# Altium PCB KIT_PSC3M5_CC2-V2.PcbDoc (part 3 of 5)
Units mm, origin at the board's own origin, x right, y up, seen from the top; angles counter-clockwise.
Board outline 131.5 x 87 mm, 6 copper layers (Top Layer, Int1 (GND), Int2 (Sign), Int3 (Sign), Int4 (PWR), Bottom Layer), stack 1.551 mm thick; 371 components, 253 nets, 1359 pads, 837 vias.
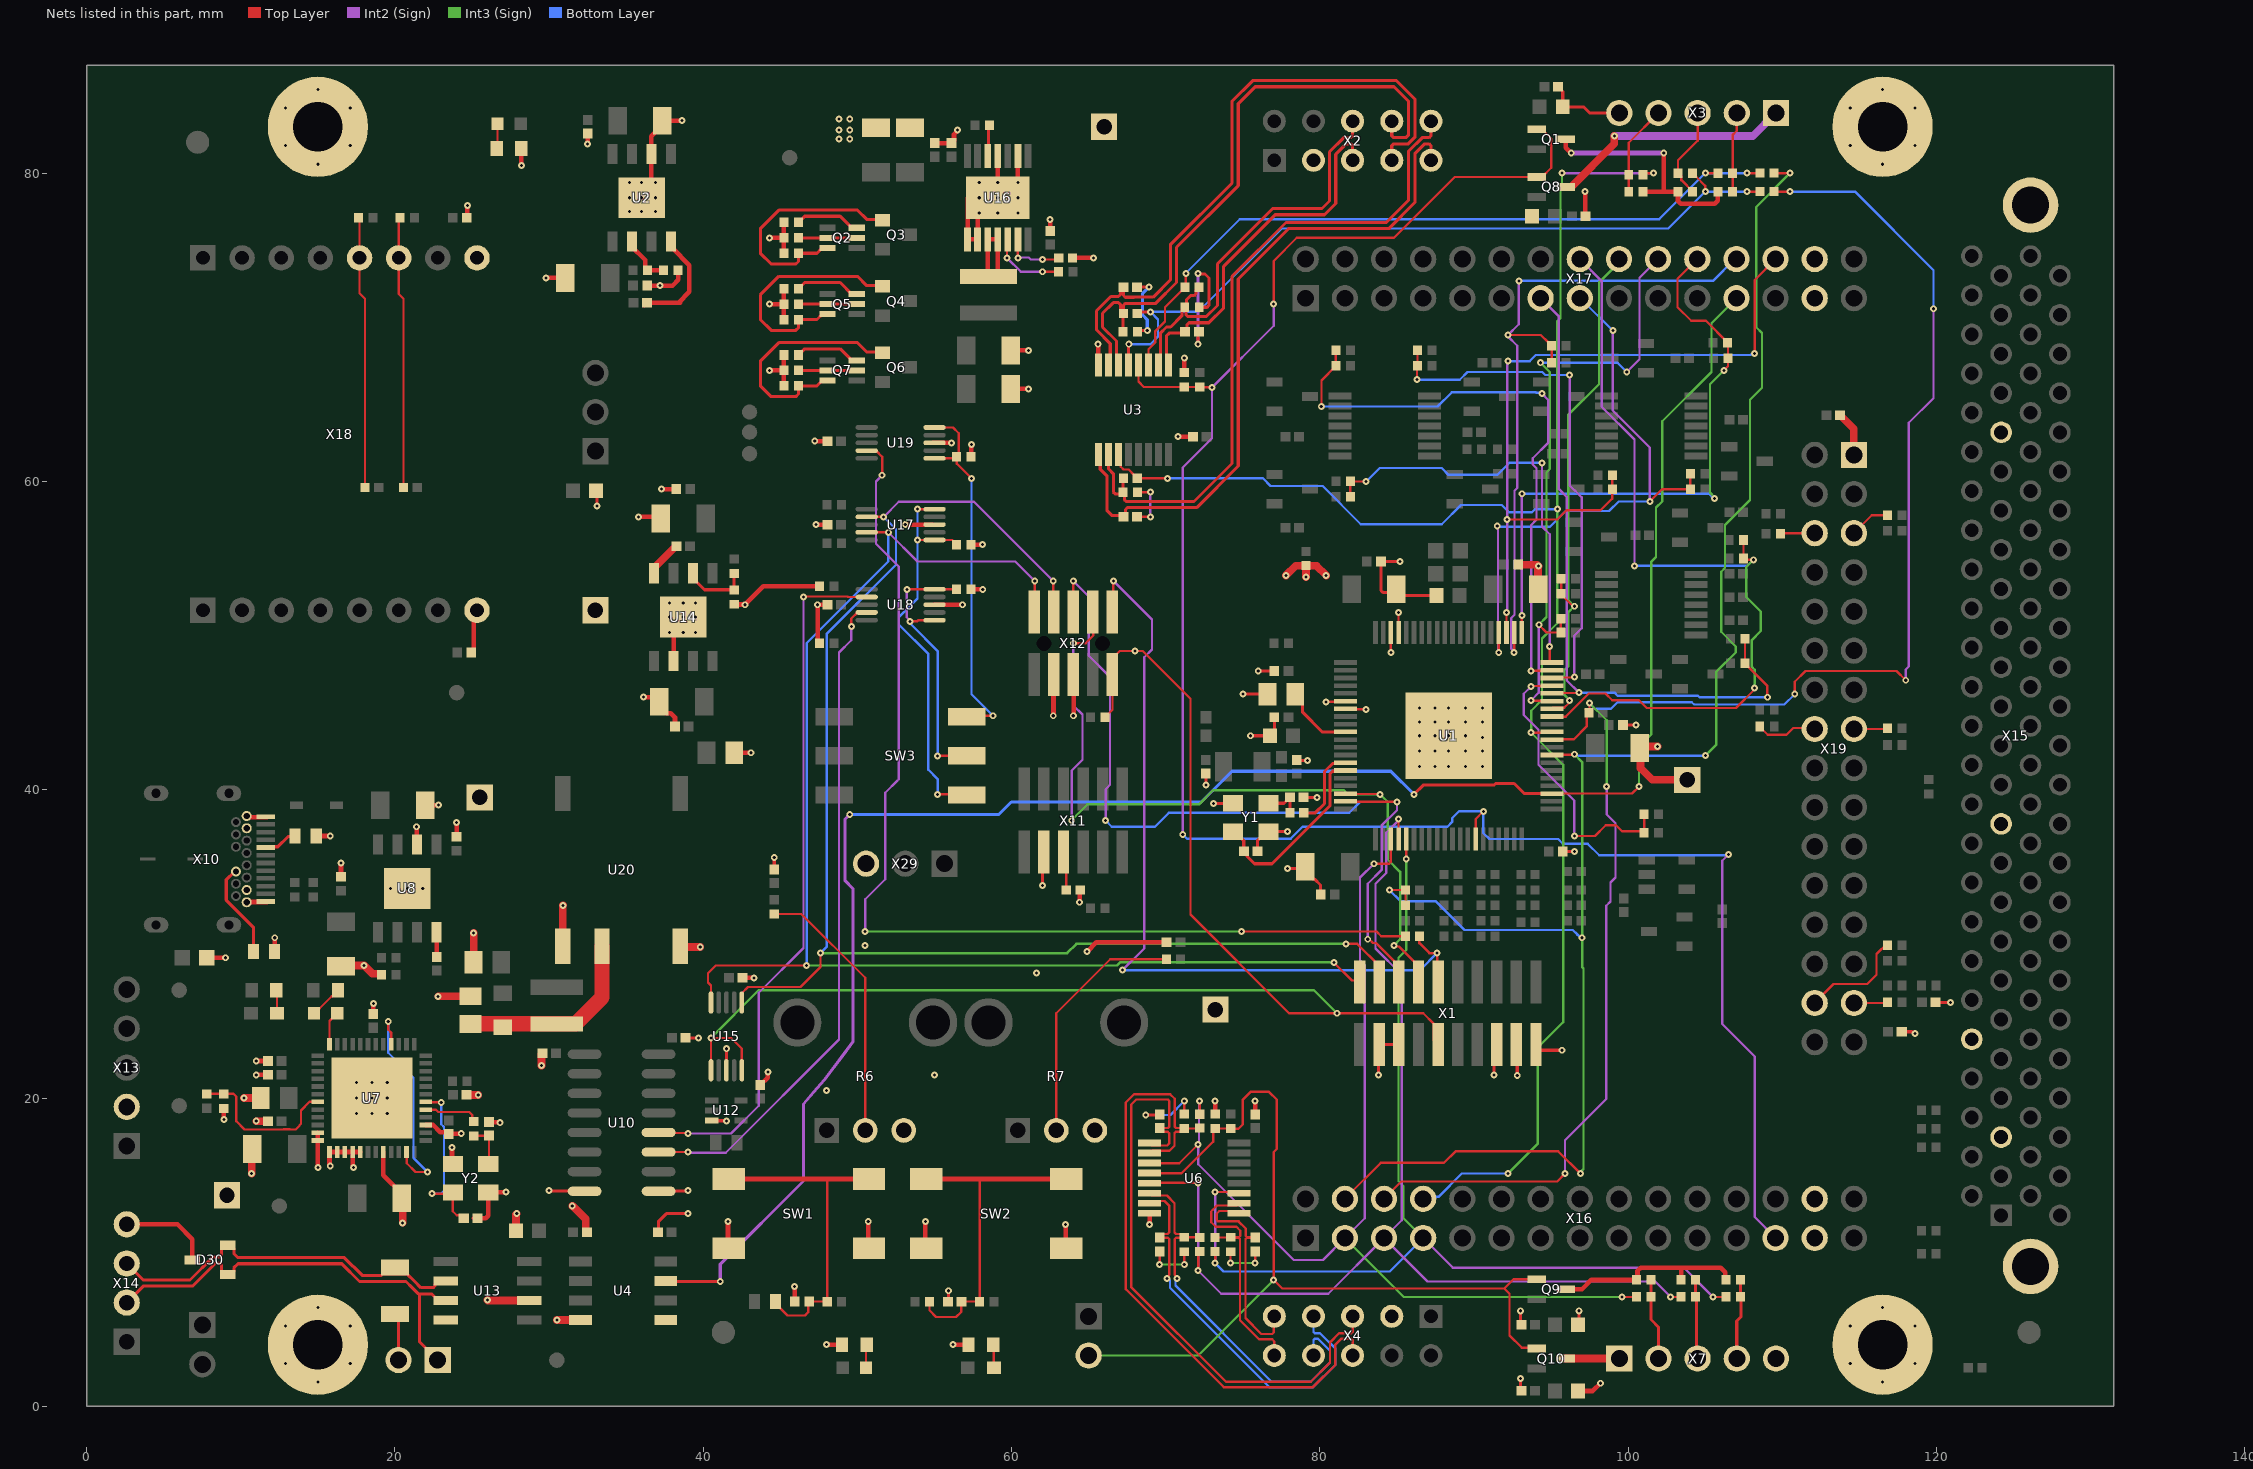
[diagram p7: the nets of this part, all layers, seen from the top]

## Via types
v1: diameter 0.45, hole 0.2, Top Layer to Bottom Layer, tented both sides, 833 vias
v2: diameter 0.55, hole 0.2, Top Layer to Bottom Layer, tented both sides, 4 vias

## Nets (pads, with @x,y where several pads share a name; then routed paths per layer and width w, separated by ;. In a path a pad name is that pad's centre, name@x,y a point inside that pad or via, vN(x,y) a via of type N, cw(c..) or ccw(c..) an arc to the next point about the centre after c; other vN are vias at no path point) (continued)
CAN1_TX: U1.43 U4.7 X17.23 | length 125.6
  Top Layer w0.15: U1.43@95.05,39.75 100.25,39.75 v1(100.7,40.2)
  Top Layer w0.2: U4.7@37.57,8.135 37.605,8.1 v1(41.1,8.1) ; v1(86.1,39.7) 86.7,40.3 91.293,40.3 91.393,40.4 92.6,40.4 93.25,39.75 U1.43@95.05,39.75
  Int2 (Sign) w0.2: v1@41.145,8.145 v1(41.1,8.1) 41.1,9.223 46.5,14.623 46.5,19.606 ccw(c11.001,50.974) 49.7,23.651 49.7,33.589 49.2,34.089 49.2,38.1 v1(49.5,38.4)
  Int3 (Sign) w0.15: v1(100.7,40.2) 100.7,42.8 101.5,43.6 101.5,54.8 101.8,55.1 101.8,58.3 102.2,58.7 102.2,63.9 105.4,67.1 105.4,70.266 X17.23@107.016,71.882
  Bottom Layer w0.2: v1(49.5,38.4) 59.186,38.4 59.986,39.2 72.3,39.2 74.3,41.2 84.6,41.2 v1(86.1,39.7)
CAN_N: D30.2 R73.2 U13.6 X14.3 | length 24.6
  Top Layer w0.2: X14.3@2.6,9.27 3.67,8.2 6.704,8.2 8.204,9.7 8.633,9.7 8.75,9.817 8.75,10.25 8.95,10.45 D30.2@9.15,10.45 9.35,10.45 9.55,10.25 9.55,9.916 9.816,9.65 16.716,9.65 17.866,8.5 19.125,8.5 19.2,8.575 R73.2@20.8,8.575 ; R73.2@20.375,9 R73.2@20.8,8.575 ; U13.6@23.3,8.135 22.8,8.135 22.6,7.935 22.6,7.817 22.483,7.7 21.783,7.7 21.679,7.7 21.279,8.1 21.275,8.1 R73.2@20.8,8.575
CAN_P: D30.1 U13.7 X14.2 X28.1 | length 28.5
  Top Layer w0.2: X14.2@2.6,6.73 3.67,7.8 6.869,7.8 8.369,9.3 8.633,9.3 8.75,9.183 8.75,8.75 8.95,8.55 D30.1@9.15,8.55 9.35,8.55 9.55,8.75 9.55,8.984 9.816,9.25 16.55,9.25 17.7,8.1 20.709,8.1 21.109,7.7 21.114,7.7 21.514,7.3 22.365,7.3 22.8,6.865 U13.7@23.3,6.865 ; 21.6,7.3 21.6,4.17 X28.1@22.77,3
CON_RESET#: R11.1 U19.9 | length 69.8
  Top Layer w0.15: U19.9@50.705,62 51.205,62 51.6,61.605 v1(51.6,60.4) ; v1(74.9,30.8) 83.672,30.8 83.972,30.5 R11.1@85.55,30.5
  Int2 (Sign) w0.15: v1(50.5,30.8) 50.5,32.9 51.8,34.2 51.8,39.8 ; v1(51.6,60.4) 51.2,60 51.2,55.96 52.675,54.485 52.675,40.675 51.8,39.8 ; 52.6,40.6 51.8,39.8
  Int3 (Sign) w0.15: v1(50.5,30.8) v1(74.9,30.8)
CON_SWDCLK: U15.6 U17.7 X1.4 X12.4 | length 92.8
  Top Layer w0.15: U15.6@42.5,26.2 42.5,26.8 42.9,27.2 46.3,27.2 47.6,28.5 v1(47.6,29.4) ; U17.7@50.705,57.7 v1(51.7,57.7) ; X12.4@62.7,51.4 v1(62.7,53.54) ; v1(81.7,30) 82.415,30 83.855,28.56 X1.4@83.855,27.535
  Int2 (Sign) w0.15: v1(51.7,57.7) 52.675,58.675 57.565,58.675 v1(62.7,53.54)
  Int3 (Sign) w0.15: v1(47.6,29.4) 63.6,29.4 64.2,30 v1(81.7,30)
  Bottom Layer w0.15: v1(47.6,29.4) 48,29.8 48,50.1 52.5,54.6 52.5,56.9 v1(51.7,57.7)
CON_SWDIO: U15.10 U17.9 X1.2 X12.2 | length 89.8
  Top Layer w0.15: U15.10@40.5,26.2 40.5,27.3 40.3,27.5 40.3,28.1 40.8,28.6 v1(46.7,28.6) ; U17.9@50.6,56.7 v1(52,56.7) ; X12.2@61.5,51.4 v1(61.5,53.54) ; v1(80.9,28.8) 82.078,27.622 82.498,27.622 X1.2@82.585,27.535
  Int2 (Sign) w0.15: v1(52,56.7) 53.895,54.805 60.235,54.805 v1(61.5,53.54)
  Int3 (Sign) w0.15: v1(46.7,28.6) 66.828,28.6 67.028,28.8 v1(80.9,28.8)
  Bottom Layer w0.15: v1(46.7,28.6) 46.7,49.5 52,54.8 v1(52,56.7) ; v1(61.5,53.54) v1@61.5,53.612
CS: U7.23 U7.40 | length 14.7
  Top Layer w0.15: v1(19.564,24.964) 19.564,24.436 19.75,24.25 U7.40@19.75,23.5 ; U7.23@20.75,16.5 20.765,16.485 20.765,15.765 21.328,15.202 v1(22.1,15.202)
  Bottom Layer w0.15: v1(19.564,24.964) 19.564,22.936 21.2,21.3 21.2,16.102 v1(22.1,15.202)
DEBUG_LED#: D5.1 U7.48 | length 2.2
  Top Layer w0.15: U7.48@15.75,23.5 15.75,25 D5.1@16.25,25.5
ECO_IN: R8.1 U1.14 | length 5.3
  Top Layer w0.2: R8.1@78.95,38.5 79.7,38.5 80.3,39.1 80.3,41.178 80.822,41.7 81.6,41.7 U1.14@81.65,41.75
ECO_OUT: C86.2 U1.15 Y1.3 | length 12.4
  Top Layer w0.2: Y1.3@74.35,37.275 74.475,37.275 75.06,36.69 C86.2@75.06,36 75.075,36 75.285,35.79 75.285,35.666 75.751,35.2 76.895,35.2 80.65,38.955 80.65,39.55 80.65,41.033 80.817,41.2 81.6,41.2 U1.15@81.65,41.25
ENC1_A_N: C74.2 U3.1 X2.5 | length 24.3
  Top Layer w0.2: U3.1@70.175,67.55 70.05,67.675 70.05,69.45 70.215,69.615 71.175,69.615 C74.2@71.26,69.7 71.384,69.824 71.384,70.177 71.501,70.294 72.794,70.294 73.75,71.25 73.75,73.95 77.1,77.3 80.3,77.3 81.025,78.025 81.025,81.213 81.712,81.9 82.003,81.9 82.12,81.783 X2.5@82.12,80.83 ; X2.5@81.521,80.637 81.687,80.637 X2.5@81.873,80.45
ENC1_A_P: R78.2 R84.2 U3.2 X2.6 | length 26.9
  Top Layer w0.2: U3.2@69.525,67.55 69.65,67.675 69.65,69.616 70.049,70.015 70.315,70.015 71.04,70.74 71.04,71.09 71.05,71.1 R84.2@71.117,71.1 ; R78.2@72.15,72.6 71.959,72.409 71.959,72.167 71.841,72.05 71.6,72.05 71.343,71.793 71.343,71.413 R84.2@71.23,71.3 71.307,71.223 71.307,70.811 71.424,70.694 72.628,70.694 73.35,71.416 73.35,74.116 76.934,77.7 80.134,77.7 80.625,78.191 80.625,81.379 81.546,82.3 82.003,82.3 82.12,82.417 X2.6@82.12,83.37
ENC1_B_N: C89.2 U3.7 X2.7 | length 41.9
  Top Layer w0.2: U3.7@66.275,67.55 66.4,67.675 66.4,68.94 65.5,69.84 65.5,71.066 66.434,72 66.933,72 67.05,72.117 67.05,72.39 C89.2@67.26,72.6 67.26,72.065 67.377,71.948 67.929,71.948 67.931,71.95 69.183,71.95 70.3,73.067 70.3,75.35 74.3,79.35 74.3,84.666 75.634,86 84.966,86 86.155,84.811 86.155,82.324 85.731,81.9 84.777,81.9 84.66,81.783 X2.7@84.66,80.83
ENC1_B_P: R79.2 R85.2 U3.6 X2.8 | length 41.2
  Top Layer w0.2: U3.6@66.925,67.55 66.8,67.675 66.8,69.106 65.9,70.006 65.9,70.9 66.6,71.6 66.933,71.6 67.05,71.483 67.05,71.1 R79.2@67.25,70.9 ; R85.2@67.23,69.7 67.23,70.88 R79.2@67.25,70.9 ; X2.8@84.66,83.37 84.66,82.417 84.777,82.3 85.566,82.3 85.755,82.489 85.755,84.645 84.8,85.6 75.8,85.6 74.7,84.5 74.7,79.184 70.7,75.184 70.7,72.901 69.349,71.55 68.097,71.55 68.095,71.548 67.377,71.548 67.26,71.431 67.26,70.91 R79.2@67.25,70.9
ENC1_Z_N: C90.2 U3.9 X2.9 | length 44.9
  Top Layer w0.2: U3.9@65.625,61.75 65.75,61.625 65.75,60.791 66.2,60.341 66.2,58.089 66.489,57.8 C90.2@67.02,57.8 ; C90.2@67.26,57.8 67.274,57.8 67.384,57.91 67.384,58.177 67.507,58.3 72,58.3 74.7,61 74.7,73.134 77.966,76.4 84.466,76.4 86.155,78.089 86.155,81.263 86.792,81.9 87.083,81.9 87.2,81.783 X2.9@87.2,80.83
ENC1_Z_P: R80.2 R86.2 U3.10 X2.10 | length 44.5
  Top Layer w0.2: U3.10@66.275,61.75 66.286,61.739 66.286,60.821 66.6,60.507 66.6,59.307 66.717,59.19 67.04,59.19 R86.2@67.23,59.38 ; R86.2@67.23,59.3 R86.2@67.23,59.38 ; R80.2@67.24,60.2 67.23,60.21 R86.2@67.23,59.38 ; X2.10@87.2,83.37 87.2,82.417 87.083,82.3 86.626,82.3 85.755,81.429 85.755,78.255 84.3,76.8 77.8,76.8 74.3,73.3 74.3,61.166 71.834,58.7 67.43,58.7 67.313,58.817 67.313,59.297 R86.2@67.23,59.38
ENC2_A_N: C94.2 U6.1 X4.5 | length 39.6
  Top Layer w0.15: U6.1@68.95,17.075 69.1,16.925 70.093,16.925 70.216,17.048 70.216,17.727 70.128,17.815 69.835,17.815 69.6,18.05 C94.2@69.6,18.06 70.143,18.06 70.231,18.148 70.231,18.802 70.225,18.808 70.225,19.812 70.137,19.9 68.088,19.9 67.75,19.562 67.75,7.75 73.9,1.6 79.4,1.6 80.65,2.85 80.65,4.15 81.245,4.745 82.032,4.745 82.12,4.833 X4.5@82.12,5.84
ENC2_A_P: R94.2 R100.2 U6.2 X4.6 | length 43
  Top Layer w0.15: U6.2@68.95,16.425 69.1,16.575 70.238,16.575 70.566,16.903 70.566,17.727 70.654,17.815 70.985,17.815 R100.2@71.2,18.03 ; R94.2@72.2,18.05 72.18,18.03 R100.2@71.2,18.03 ; X4.6@82.12,3.3 82.12,4.307 82.032,4.395 81.39,4.395 81,4.005 81,2.705 79.545,1.25 73.755,1.25 67.4,7.605 67.4,19.707 67.943,20.25 70.282,20.25 70.575,19.957 70.575,18.953 70.581,18.947 70.581,18.148 70.669,18.06 71.17,18.06 R100.2@71.2,18.03
ENC2_B_N: C95.2 U6.7 X4.7 | length 25.9
  Top Layer w0.15: U6.7@68.95,13.175 69.1,13.325 69.713,13.325 69.925,13.325 70.216,13.034 70.216,11.273 70.128,11.185 69.835,11.185 69.6,10.95 C95.2@69.6,10.94 70.143,10.94 70.231,10.852 70.231,9.593 70.225,9.587 70.225,8.545 70.075,8.395 v1(70.075,8.3)
  Bottom Layer w0.15: v1(70.075,8.3) 70.137,8.3 70.275,8.162 70.275,7.688 76.713,1.25 78.216,1.25 79.55,1.25 81,2.7 81,3.747 80.002,4.745 79.668,4.745 79.58,4.833 X4.7@79.58,5.84
ENC2_B_P: R95.2 R101.2 U6.6 X4.8 | length 25.7
  Top Layer w0.15: U6.6@68.95,13.825 69.1,13.675 70.07,13.675 70.566,13.179 70.566,11.273 70.654,11.185 70.985,11.185 R101.2@71.2,10.97 ; v1(70.725,8.3) 70.725,8.395 70.575,8.545 70.575,9.442 70.581,9.448 70.581,10.852 70.669,10.94 71.17,10.94 R101.2@71.2,10.97 ; R95.2@72.2,10.95 72.18,10.97 R101.2@71.2,10.97
  Bottom Layer w0.15: v1(70.725,8.3) 70.725,8.219 70.625,8.119 70.625,7.833 76.858,1.6 79.405,1.6 80.65,2.845 80.65,3.602 79.857,4.395 79.668,4.395 79.58,4.307 X4.8@79.58,3.3
ENC2_Z_N: C96.2 U6.9 X4.9 | length 14.4
  Top Layer w0.15: U6.9@74.75,12.525 74.6,12.675 73.475,12.675 73.3,12.5 73.3,12.088 73.388,12 74.725,12 75.181,11.544 75.181,11.058 75.269,10.97 75.77,10.97 C96.2@75.8,10.94 75.257,10.94 75.169,10.852 75.169,5.726 76.195,4.7 76.37,4.7 76.912,4.7 77,4.788 77,5.8 X4.9@77.04,5.84
ENC2_Z_P: R96.2 R102.2 U6.10 X4.10 | length 16.5
  Top Layer w0.15: R96.2@73.2,10.95 74.18,10.95 R102.2@74.2,10.97 ; U6.10@74.75,13.175 74.6,13.025 73.33,13.025 73.053,12.747 72.95,12.645 72.95,11.943 73.243,11.65 74.58,11.65 74.831,11.399 74.831,11.058 74.743,10.97 R102.2@74.2,10.97 ; X4.10@77.04,3.3 77.04,4.21 76.9,4.35 76.662,4.35 76.05,4.35 74.819,5.581 74.819,10.852 74.731,10.94 74.23,10.94 R102.2@74.2,10.97
GND: C1.1 C2.1 C3.1 C4.1 C5.1 C6.1 C7.1 C8.1 C9.1 C10.1 C11.1 C13.1 C14.1 C15.1 C16.1 C17.1 C18.1 C20.2 C28.1 C29.2 C32.2 C33.1 C34.1 C35.1 C36.1 C37.1 C38.1 C39.1 C40.1 C65.1 C70.1 C73.1 C75.1 C76.1 C77.1 C78.2 C80.1 C81.1 C82.1 C85.1 C86.1 C100.1 C101.1 C102.2 C103.1 C104.1 C105.1 C106.1 C107.1 C124.1 C125.1 C127.1 C128.1 C129.1 C130.1 C131.1 C135.2 C136.2 C137.2 C138.2 C139.2 MH2.1 MH3.1 MH4.1 R3.2 R6.3 R7.3 R52.1 R54.2 R63.1 R64.2 R65.1 R66.1 R67.1 R68.2 R69.1 R71.1 R77.1 R93.1 R108.1 R109.2 R110.2 R111.2 R128.1 R129.1 R130.1 R132.1 R134.1 R150.1 R152.1 SW1.1 SW1.2 SW2.1 SW2.2 U1.6 U1.7 U1.77 U1.78 U1.81 U2.6 U2.9 U3.8 U4.5 U6.8 U10.9 U12.3 U14.6 U14.9 U15.3 U16.2 U16.4 U16.8 U16.9 U16.15 U17.3 U18.3 U19.3 U20.4 X1.3 X1.5 X1.15 X1.17 X1.19 X2.3 X3.5 X4.3 X7.5 X11.3 X12.3 X12.5 X15.A5 X15.A10 X15.A21 X15.A41 X15.MH1 X15.MH2 X16.27 X16.28 X17.27 X17.28 X18.8 X18.9 X19.1 X24.1 X25.1 X26.1 X27.1 X29.3 Y1.2 Y1.4 | length 177.3
  Top Layer w0.15: v1(80.4,45.7) U1.6@81.7,45.7 ; U1.7@81.6,45.2 81.625,45.225 82.975,45.225 v1(83,45.2) ; v1(84.6,48.9) U1.78@84.6,50.2 ; U1.77@85.1,50.2 v1(85.1,51.5)
  Top Layer w0.2: C107.1@33.05,59.4 33.1,59.35 v1(33.1,58.4) ; C20.2@37.075,11.3 37.086,11.311 37.086,11.986 37.6,12.5 v1(39,12.5) ; U10.9@37.1,13.955 37.123,13.978 38.978,13.978 v1(39,14) ; C65.1@38.84,23.9 v1(39.7,23.9) ; U12.3@40.55,18.55 40.575,18.525 41.475,18.525 v1(41.5,18.5) ; U15.3@41.5,21.8 v1(41.5,23.2) ; C135.2@44.6,34.84 v1(44.6,35.6) ; R66.1@45.215,70.515 R66.1@45.23,70.5 ; C137.2@55.86,6.8 55.9,6.84 v1(55.9,7.5) ; v1(62,33.8) 62,35.87 X11.3@62.095,35.965 ; v1(72.6,40.3) C73.1@72.6,41.06 ; v1(73.1,39.1) 74.325,39.1 Y1.2@74.35,39.125 ; v1(75,46.2) C18.1@76.6,46.2 ; v1(75.5,43.5) C2.1@76.75,43.5 77.04,43.79 C1.1@77.04,44.7 ; C86.1@75.94,36 75.94,36.69 76.525,37.275 Y1.4@76.65,37.275 76.675,37.3 v1(77.9,37.3) ; v1(76,47.7) C8.1@77.04,47.7 ; v1(77.9,34.9) 78.95,34.9 C3.1@79.05,35 79.05,34.7 79.55,34.2 79.66,34.2 80.04,33.82 C10.1@80.04,33.2 ; C70.1@78.5,41.94 78.539,41.901 v1(79.199,41.901) ; C85.1@78.94,39.5 v1(79.8,39.5) ; v1(83.8,21.5) 83.8,23.41 X1.3@83.855,23.465 X1.5@85.125,23.465 ; v1(85.2,54.8) C6.1@83.96,54.8 83.96,52.917 84.077,52.8 84.75,52.8 C5.1@84.95,53 85.35,52.6 C17.1@87.45,52.6 ; v1(91.3,21.5) 91.3,23.29 X1.15@91.475,23.465 ; X1.17@92.745,23.465 92.798,23.412 v1(92.798,21.473) ; v1(93,1.8) 93,1.06 C40.1@93.06,1 ; v1(93,6.2) 93,5.171 C36.1@93.065,5.105 ; X1.19@94.015,23.465 94.015,23.37 94.285,23.1 v1(95.7,23.1) ; C34.1@95.44,85.6 95.455,85.6 95.665,85.39 95.665,85.375 95.75,85.29 C33.1@95.75,84.3 97.1,84.3 97.5,83.9 X3.5@99.42,83.9 ; C7.1@95.76,36 v1(96.5,36) ; C35.1@96.8,5.15 v1(96.8,6.2) ; C9.1@99.66,44.2 v1(100.5,44.2) ; C138.2@117.74,24.3 118.419,24.3 118.519,24.2 v1(118.6,24.2) ; C139.2@119.94,26.2 v1(120.9,26.2)
  Top Layer w0.3: C76.1@24.66,77.1 24.68,77.12 24.68,77.88 v1(24.7,77.9) ; C75.1@24.96,48.9 25.12,49.06 25.12,51.44 X18.8@25.32,51.64 ; v1(28.2,80.5) R111.2@28.2,81.6 ; v1(29.8,73.2) C15.1@31.05,73.2 ; v1(32.5,81.9) C131.1@32.5,82.56 ; v1(35.8,57.7) 37.15,57.7 C128.1@37.25,57.6 ; v1(36.111,46.011) 36.839,46.011 C130.1@37.15,45.7 37.15,45.4 37.6,44.95 37.9,44.95 38.16,44.69 C129.1@38.16,44.1 ; C14.1@36.36,72.7 v1(37.2,72.7) ; U2.9@36.617,79.683 v1(36.9,79.4) ; U2.9@36.635,79.035 U2.6@36.635,81.245 36.635,82.385 37.35,83.1 C13.1@37.35,83.4 v1(38.615,83.4) ; v1@37.1,72.7 38,72.7 38.37,73.07 R134.1@38.37,73.7 ; v1(37.3,59.5) C127.1@38.24,59.5 ; v1(37.8,50.2) 38.082,49.917 38.082,48.372 U14.6@38.065,48.355 ; v1(41.6,12) 41.6,10.3 SW1.2@41.65,10.25 ; C80.1@42,42.55 42.15,42.4 v1(43.1,42.4) ; R132.1@42,52.03 42.015,52.015 42.685,52.015 v1(42.7,52) 43.9,53.2 R150.1@47.53,53.2 ; C81.1@42.54,27.8 v1(43.3,27.8) ; C77.1@43.7,20.84 43.7,20.855 44.171,21.326 44.171,21.671 v1(44.2,21.7) ; v1(44.3,67.2) R68.2@45.23,67.2 ; v1(44.3,71.5) R54.2@45.23,71.5 ; v1(44.3,75.8) R64.2@45.23,75.8 ; R54.2@45.13,71.6 R54.2@45.23,71.5 ; R67.1@45.23,66.2 R68.2@45.23,67.2 ; R69.1@45.23,68.2 R68.2@45.23,67.2 ; R66.1@45.23,70.5 R54.2@45.23,71.5 ; R65.1@45.23,74.8 R64.2@45.23,75.8 ; R63.1@45.23,76.8 R64.2@45.23,75.8 ; R52.1@45.33,72.5 R52.1@45.23,72.5 R54.2@45.23,71.5 ; C28.1@45.92,6.82 v1(45.92,7.78) ; v1@47.25,62.6 C82.1@48.01,62.6 ; v1(47.3,57.2) C124.1@48.06,57.2 ; R152.1@47.53,49.5 47.429,49.601 47.429,51.971 v1(47.4,52) C125.1@48.06,52 ; v1(48,4) 48.98,4 R109.2@48.99,3.99 ; v1(50.7,12) 50.7,10.3 SW1.1@50.75,10.25 ; v1(53.1,57.2) U17.3@54.896,57.2 ; v1(54.4,12) 54.4,10.3 SW2.2@54.45,10.25 ; U19.3@54.896,62.5 U19.3@55,62.5 v1(56.1,62.5) ; U18.3@55,52 v1(56.8,52) ; C103.1@55,81.94 C102.2@56.1,81.94 56.26,82.1 56.26,82.519 56.5,82.759 v1(56.5,82.8) ; v1(56.2,4) 57.18,4 R110.2@57.19,3.99 ; R128.1@57.37,55.9 v1(58.1,55.9) ; R130.1@57.37,61.6 57.385,61.615 57.385,62.385 v1(57.4,62.4) ; R129.1@57.44,53 v1(58.125,53) ; v1(57.9,77.4) 57.8,77.3 U16.9@57.8,75.7 U16.8@57.15,75.7 57.15,78.4 v1(57.9,78.4) ; v1(59.1,79.4) U16.4@59.1,81.1 ; C106.1@59.95,66 v1(61.1,66) ; C105.1@60.05,68.5 v1(61.1,68.5) ; v1(60.4,79.4) U16.2@60.4,81.1 ; C104.1@62.5,76.24 v1(62.5,77) ; v1(62.7,44.8) 62.715,44.815 62.715,47.42 X12.3@62.73,47.435 ; v1(63.5,11.8) 63.5,10.3 SW2.1@63.55,10.25 ; R108.1@63.95,74.5 v1(65.3,74.5) ; v1@64.03,44.83 X12.5@64.03,47.435 ; v1(64.4,32.7) 64.425,32.725 64.425,33.475 R3.2@64.45,33.5 ; v1(64.9,29.5) 65.5,30.1 C136.2@70.06,30.1 ; v1(65.6,68.9) 65.613,68.888 65.613,67.562 U3.8@65.625,67.55 ; v1(68.95,11.8) U6.8@68.95,12.525 ; v1(70.8,62.9) C29.2@71.76,62.9 ; R77.1@71.2,67.07 v1(71.2,68) ; R93.1@73.2,18.97 v1(73.2,19.8) ; C32.2@75.8,18.94 v1(75.8,19.8) ; C37.1@93.7,77.25 C37.1@93.75,77.2 ; C39.1@96.75,1 97.7,1 v1(98.2,1.5) ; v1(97.2,78.8) 97.22,78.78 97.22,77.22 C38.1@97.24,77.2
  Top Layer w0.5: U20.4@38.51,29.8 v1(39.8,29.8) ; v1(77.8,53.9) 78.429,54.529 R71.1@79.079,54.529 ; v1(79.1,53.8) R71.1@79.1,54.55 ; R71.1@79.121,54.529 79.771,54.529 v1(80.4,53.9) ; C16.1@92.86,54.6 94.075,54.6 v1(94.175,54.5) 94.15,54.475 C11.1@94.15,53 ; v1(101.9,42.8) 100.85,42.8 C4.1@100.75,42.7 100.8,42.65 100.8,41.4 101.56,40.64 X27.1@103.82,40.64 ; C78.2@113.74,64.3 113.755,64.3 114.636,63.419 X19.1@114.636,61.722
  other v1: 116.5,1.575 114.4,2.787 118.6,2.787 114.4,5.212 118.6,5.212 116.5,6.425 48,20.5 55,21.5 61.625,28.125 50.5,29.9 86.45,41.5 87.45,41.5 88.35,41.5 89.45,41.5 90.55,41.5 86.45,42.5 87.45,42.5 88.35,42.5 89.45,42.5 90.55,42.5 90.55,43.4 86.45,43.5 87.45,43.5 88.35,43.5 89.45,43.5 86.45,44.4 87.45,44.4 88.35,44.4 89.45,44.4 90.55,44.4 64,44.8 86.45,45.3 87.45,45.3 88.35,45.3 89.45,45.3 90.55,45.3 38.7,50.2 39.5,50.2 37.8,51.2 38.7,51.2 39.5,51.2 37.8,52.1 38.7,52.1 39.5,52.1 47.23,62.62 59.1,77.4 60.4,77.4 35.2,77.5 36,77.5 36.9,77.5 35.2,78.4 36,78.4 36.9,78.4 59.1,78.4 60.4,78.4 35.2,79.4 36,79.4 57.9,79.4 15,80.575 116.5,80.575 12.9,81.787 17.1,81.787 114.4,81.787 118.6,81.787 48.8,82.2 49.5,82.2 48.8,82.8 49.5,82.8 48.8,83.5 49.5,83.5 12.9,84.212 17.1,84.212 114.4,84.212 118.6,84.212 15,85.425 116.5,85.425
GNDISO: C19.2 C21.1 C42.1 C43.1 C44.1 C45.1 C46.1 C47.1 C48.1 C49.1 C50.1 C51.1 C52.1 C53.1 C62.1 C63.1 C64.1 C87.1 C88.1 C132.1 D30.3 L1.1 MH1.1 R18.1 R21.2 R24.1 R146.1 U4.4 U7.11 U7.12 U7.13 U7.14 U7.15 U7.16 U7.17 U7.20 U7.27 U7.49 U8.6 U8.9 U10.8 U13.2 U13.8 U20.1 X10.A1 X10.A12 X10.B1 X10.B12 X10.G1 X10.G2 X13.2 X14.4 X22.1 X23.1 Y2.2 Y2.4 | length 61.7
  Top Layer w0.15: C46.1@11.73,21.532 C46.1@11.76,21.502
  Top Layer w0.2: v1(30,14) 30.023,13.978 U10.8@32.377,13.978
  Top Layer w0.3: X14.4@2.6,11.81 5.89,11.81 6.85,10.85 D30.3@6.85,9.5 ; L1.1@7.8,29.1 v1(9,29.1) ; v1(8.902,18.602) R24.1@8.902,19.332 ; X10.B1@10.45,32.67 10.5,32.72 X10.A12@11.7,32.72 ; X10.B12@10.45,38.27 10.5,38.22 X10.A1@11.7,38.22 ; v1(11,21.502) C46.1@11.76,21.502 ; v1(11,22.402) C50.1@11.76,22.402 ; R21.2@12.19,29.5 12.195,29.505 12.195,30.395 v1(12.2,30.4) ; R18.1@14.99,37 v1(15.8,37) ; v1(15,15.502) U7.12@15,17.25 U7.11@15,17.75 ; v1(15.8,15.602) 15.8,15.643 15.75,15.693 U7.13@15.75,16.5 U7.14@16.25,16.5 U7.15@16.75,16.5 U7.16@17.25,16.5 ; C44.1@16.5,28.55 C44.1@16.55,28.6 ; C43.1@16.5,34.36 v1@16.5,35.23 ; v1(17.3,15.5) 17.3,15.554 17.25,15.604 U7.16@17.25,16.5 ; U7.17@17.75,16.5 U7.16@17.25,16.5 ; C49.1@18.6,25.44 v1(18.6,26.125) ; U7.20@19.25,16.5 19.25,15 20.505,13.745 C45.1@20.505,13.495 ; v1(21.4,37.6) 21.418,37.582 21.418,36.463 U8.6@21.435,36.445 ; C42.1@21.95,39 v1@22.82,39 ; U7.27@22,18.25 22.474,18.25 22.946,17.778 23.382,17.778 C48.1@23.5,17.66 23.52,17.68 24.28,17.68 v1(24.3,17.7) ; v1(23.7,16.8) 23.7,15.775 Y2.2@23.75,15.725 ; C132.1@24,37 v1@24,37.87 ; C88.1@25.122,12.202 25.874,12.202 26.05,12.378 Y2.4@26.05,13.875 26.075,13.9 v1(27.2,13.9) ; C87.1@26.1,18.44 26.12,18.42 26.78,18.42 v1(26.8,18.4)
  Top Layer w0.5: v1(10.2,20.002) C51.1@11.3,20.002 ; v1(10.7,15.102) 10.7,16.652 C47.1@10.75,16.702 ; v1(11,18.502) C52.1@11.76,18.502 ; C44.1@16.55,28.6 v1(18,28.6) 18.54,28.06 19.09,28.06 19.13,28.02 R146.1@19.13,28 ; C45.1@20.45,13.5 20.5,13.45 v1(20.5,11.902) ; v1(22.8,26.6) C62.1@24.9,26.6 ; C53.1@24.64,20.2 v1(25.4,20.2) ; C64.1@25.1,29.2 v1(25.1,30.7) ; v1(26,6.9) 26.035,6.865 U13.2@28.7,6.865 ; C21.1@27.85,11.4 27.85,12.45 v1(27.9,12.5) ; v1(29.5,22.1) 29.5,22.84 C63.1@29.56,22.9 ; v1(30.5,5.6) 32.025,5.6 U4.4@32.03,5.595 ; U20.1@30.89,29.845 30.89,32.49 v1(30.9,32.5) ; v1(31.5,13) 31.519,13 32.365,12.154 32.365,11.36 32.425,11.3 C19.2@32.44,11.3
  other v1: 15,1.575 12.9,2.787 17.1,2.787 12.9,5.212 17.1,5.212 15,6.425 17.5,19 18.5,19 19.5,19 17.5,20 18.5,20 19.5,20 17.5,21 18.5,21 19.5,21 19.7,33.6 20.8,33.6 21.8,33.6 16.485,35.245 23.985,37.885 22.835,39.015
IPFC1_IL0: R42.2 R139.2 U1.58 | length 33.6
  Top Layer w0.15: v1(86.3,66.6) 86.3,67.47 R42.2@86.33,67.5 R139.2@86.33,68.5 ; U1.58@95.125,47.275 96.475,47.275 v1(96.5,47.3)
  Int2 (Sign) w0.15: v1(96.2,66.9) 96.2,59.728 96.541,59.387 96.559,59.387 96.975,58.972 96.975,50.475 96.5,50 v1(96.5,47.3)
  Bottom Layer w0.15: v1(86.3,66.6) 89.072,66.6 89.572,67.1 94.422,67.1 94.622,66.9 v1(96.2,66.9)
IPFC2_IL1: R44.2 R138.2 U1.59 | length 39
  Top Layer w0.15: v1(80.087,64.861) 80.1,64.874 80.1,66.55 81.03,67.48 R44.2@81.03,67.5 R138.2@81.03,68.5 ; v1(93.7,47.7) 93.725,47.725 95.075,47.725 U1.59@95.1,47.7
  Int2 (Sign) w0.15: v1(93.7,47.7) 93.7,57.173 94.05,57.523 94.05,60.85 93.8,61.1 93.8,61.5 94.8,62.5 94.8,65.3 v1(94.4,65.7)
  Bottom Layer w0.15: v1(80.087,64.861) 87.633,64.861 88.547,65.775 93.997,65.775 94.014,65.757 94.343,65.757 v1(94.4,65.7)
IPFC_Iac: R46.2 R137.2 U1.60 | length 27.7
  Top Layer w0.15: R137.2@81.97,59 R46.2@81.97,60 v1(83,60) ; v1(94.9,49.3) 94.9,48.325 94.95,48.275 U1.60@95.225,48.275
  Int2 (Sign) w0.15: v1(94.4,61.2) 94.4,57.072 94.9,56.572 v1(94.9,49.3)
  Bottom Layer w0.15: v1(83,60) 83.875,60.875 87.897,60.875 88.347,60.425 91.503,60.425 92.292,61.214 94.386,61.214 v1(94.4,61.2)
ISO_DISABLE: R14.1 U15.1 U15.5 X1.9 X12.9 | length 93
  Top Layer w0.15: U15.1@40.5,21.8 v1(40.5,23.9) 41.812,23.9 42.5,23.212 U15.5@42.5,21.8 ; R14.1@66.07,44.7 66.07,44.72 66.54,45.19 X12.9@66.54,47.465 66.8,48.785 67.015,49 v1(68,49) 68.5,49 71.6,45.9 71.6,31.9 78,25.5 v1(81.1,25.5) 86.7,25.5 87.37,24.83 87.37,23.76 X1.9@87.665,23.465
  Int3 (Sign) w0.15: v1(40.5,23.9) 43.6,27 79.6,27 v1(81.1,25.5)
ISO_RX: U10.11 U18.9 | length 43.7
  Top Layer w0.15: U10.11@37.1,16.495 37.103,16.498 38.998,16.498 v1(39,16.5) ; v1(49.6,50.6) 49.6,51.105 49.995,51.5 U18.9@50.705,51.5
  Int2 (Sign) w0.15: v1(39,16.5) 39.043,16.457 41.457,16.457 48.8,23.8 48.8,48.9 49.6,49.7 v1(49.6,50.6)
ISO_TX: U10.12 U18.7 | length 45.7
  Top Layer w0.15: U10.12@37.1,17.765 37.132,17.732 38.968,17.732 v1(39,17.7) ; v1(46.5,52.5) 46.535,52.535 49.358,52.535 49.393,52.5 U18.7@50.705,52.5
  Int2 (Sign) w0.15: v1(39,17.7) 41.8,17.7 43.6,19.5 43.6,26.824 46.5,29.724 v1(46.5,52.5)
JTAG_TDI: U1.18 X1.8 X12.8 | length 52
  Top Layer w0.15: v1(64,49.5) 64.8,49.5 65.3,50 X12.8@65.3,51.7 ; U1.18@81.825,39.725 83.875,39.725 v1(83.9,39.7) ; v1(84.8,29.9) 84.867,29.833 85.122,29.833 86.395,28.56 X1.8@86.395,27.535
  Int2 (Sign) w0.15: v1(63.9,38) 63.9,41.246 64.6,41.946 64.6,44.872 64,45.472 v1(64,49.5)
  Int3 (Sign) w0.15: v1(63.9,38) 63.9,38.042 64.907,39.049 72.149,39.049 73.075,39.975 81.546,39.975 81.821,39.7 v1(83.9,39.7) 84.4,39.2 84.4,35.472 85.2,34.672 85.2,30.3 v1(84.8,29.9)
JTAG_TDO_SWO: U1.19 X1.6 X12.6 | length 55.4
  Top Layer w0.15: X12.6@64,51.4 v1(64,53.54) ; U1.19@81.625,39.225 84.975,39.225 v1(85,39.2) ; v1(83.1,30.3) 83.195,30.3 83.441,30.054 83.631,30.054 85.125,28.56 X1.6@85.125,27.535
  Int2 (Sign) w0.15: v1(64,53.54) 65,52.54 65,48.7 66.38,47.32 66.38,40.323 66.1,40.043 v1(66.1,38) ; v1(83.1,30.3) 83.1,33.9 84,34.8 84,37.672 85,38.672 v1(85,39.2)
  Int3 (Sign) w0.15: v1@84.933,39.267 v1(85,39.2)
  Bottom Layer w0.15: v1@66.102,37.998 66.5,37.6 69.3,37.6 70.2,38.5 81.9,38.5 82.6,39.2 v1(85,39.2)
M1_ENENC_M: Q1.1 Q8.1 R75.1 R77.2 U1.34 U3.4 X16.25 | length 136.3
  Top Layer w0.15: U3.4@68.225,67.55 68.225,66.475 68.57,66.13 R77.2@71.2,66.13 R75.1@72.2,66.13 ; R75.1@72.4,66.13 R75.1@72.2,66.13 ; v1(73,66.1) 72.23,66.1 R75.1@72.2,66.13 ; v1(77,71.5) 77,74.3 78.5,75.8 84.8,75.8 88.75,79.75 Q8.1@94.05,79.75 94.4,79.75 95,80.35 95,82.25 94.4,82.85 Q1.1@94.05,82.85 ; U1.34@90.1,36.8 90.1,38.1 v1(90.6,38.6)
  Int2 (Sign) w0.15: v1(71.1,37.1) 71.1,60.9 73,62.8 v1(73,66.1) 77,70.1 v1(77,71.5) ; v1(106.5,35.8) 106.1,35.4 106.1,24.8 108.2,22.7 108.2,12.278 X16.25@109.556,10.922
  Bottom Layer w0.15: v1(71.1,37.1) 71.375,36.825 78.097,36.825 78.872,37.6 88.272,37.6 88.575,37.903 88.575,38.147 89.028,38.6 v1(90.6,38.6) 90.6,37.2 91,36.8 95.453,36.8 95.753,36.5 97.364,36.5 98.114,35.75 106.45,35.75 v1(106.5,35.8)
M1_H/E_A: R4.2 R78.1 R151.1 U3.3 | length 47.8
  Top Layer w0.15: U3.3@68.875,67.55 68.875,68.575 69.325,69.025 69.325,69.75 69.95,70.375 69.95,71.3 R78.1@71.25,72.6 71.3,72.65 v1(71.3,73.5) ; v1(105,80) 105.65,80 R151.1@105.83,80.18 ; v1(107.7,80) R4.2@108.55,80
  Bottom Layer w0.15: v1(71.3,73.5) 74.8,77 102,77 v1(105,80) v1(107.7,80)
M1_H/E_B: R13.2 R79.1 R153.1 U3.5 | length 50.5
  Top Layer w0.15: R153.1@104.17,80 104.17,79.98 104.385,79.765 104.405,79.765 105,79.17 v1(105,78.8) ; v1(107.7,78.8) R13.2@108.55,78.8
  Top Layer w0.2: U3.5@67.575,67.55 67.588,67.562 67.588,68.888 v1(67.6,68.9) ; R79.1@68.15,70.9 68.25,71 v1(69,71)
  Int2 (Sign) w0.2: v1@68.993,71 v1(69,71)
  Bottom Layer w0.15: v1(67.6,68.9) 69,68.9 69.5,69.4 69.5,70.5 v1(69,71) 72.104,71 77.504,76.4 102.6,76.4 v1(105,78.8) v1(107.7,78.8)
M1_HALL1/Encoder_A: R4.1 R15.1 R97.2 U1.48 X16.4 | length 112.7
  Top Layer w0.15: X16.4@81.616,13.462 83.954,15.8 88.05,15.8 88.79,16.54 95.46,16.54 v1(96.9,15.1) ; v1(84.5,33.5) R97.2@85.55,33.5 R15.1@85.55,32.5 ; U1.48@95.025,42.225 95.075,42.275 96.475,42.275 v1(96.5,42.3) ; R4.1@109.45,80 v1(110.5,80)
  Int2 (Sign) w0.15: X16.4@81.616,13.462 X16.4@81.616,13.548
  Int3 (Sign) w0.15: v1(96.5,42.3) 97.025,41.775 97.025,30.4 97.025,28.483 97.1,28.408 97.1,15.395 96.9,15.195 v1(96.9,15.1) ; v1(105.014,42.214) 105.7,42.9 105.7,47.628 106.975,48.903 106.975,49.297 106.025,50.247 106.025,54.147 106.275,54.397 106.275,57.175 107.9,58.8 107.9,65.296 108.675,66.071 108.675,69.625 108.3,70 108.3,77.8 v1(110.5,80)
  Bottom Layer w0.15: v1(84.5,33.5) 85.225,32.775 87.501,32.775 89.376,30.9 96.4,30.9 96.7,30.6 96.705,30.6 96.905,30.4 v1(97,30.4) ; v1@96.681,42.214 v1(105.014,42.214)
M1_HALL2/Encoder_B: R13.1 R98.2 U1.50 X16.6 | length 111.7
  Top Layer w0.15: X16.6@84.156,13.462 85.281,14.587 95.387,14.587 v1(95.9,15.1) ; U1.50@95.05,43.25 95.075,43.275 96.475,43.275 97.3,44.1 97.3,45.15 R98.2@97.25,45.2 ; R98.2@97.45,45 97.486,45.036 v1(97.486,45.614) ; R13.1@109.45,78.8 v1(110.5,78.8) ; v1(110.8,46.2) 110.8,47 111.5,47.7 117.4,47.7 v1(118,47.1)
  Int2 (Sign) w0.15: v1(95.9,15.1) 95.9,17.258 98.575,19.933 98.575,32.476 98.85,32.751 98.85,33.986 99.175,34.311 99.175,37.825 98.6,38.4 v1(98.6,40.2) ; v1(118,47.1) 118,47.8 118.2,48 118.2,63.8 119.8,65.4 v1(119.8,71.2)
  Int3 (Sign) w0.15: v1(97.486,45.614) 98.6,44.5 v1(98.6,40.2)
  Bottom Layer w0.15: v1(97.486,45.614) 97.85,45.25 98.874,45.25 99.299,45.675 104.125,45.675 104.275,45.525 110.125,45.525 v1(110.8,46.2) ; v1(110.5,78.8) 114.7,78.8 119.8,73.7 v1(119.8,71.2)
M1_HALL3/Encoder_Z/Index: R80.1 R155.1 U1.51 U3.11 X16.8 | length 113.8
  Top Layer w0.15: U3.11@66.925,61.75 67.075,61.6 67.075,60.957 67.257,60.775 67.593,60.775 67.775,60.593 67.775,60.575 R80.1@68.15,60.2 v1(70.1,60.2) ; v1(93.7,43.7) U1.51@95,43.7 ; R155.1@100.97,79.9 101.07,80 v1(101.65,80)
  Int2 (Sign) w0.15: v1(95.7,80) v1(101.65,80)
  Int3 (Sign) w0.15: v1(92.2,15.1) 94.119,17.019 94.119,23.261 95.775,24.917 95.775,41.625 v1(93.7,43.7) 93.7,45.128 94.41,45.838 94.41,49.81 95.4,50.8 95.4,70.4 95.6,70.6 95.6,79.2 95.7,79.3 v1(95.7,80)
  Bottom Layer w0.15: v1(70.1,60.2) 76.3,60.2 76.8,59.7 80.178,59.7 82.653,57.225 87.897,57.225 89.147,58.475 91.797,58.475 92.272,58 93.747,58 93.947,58.2 v1(95.4,58.2) ; X16.8@86.696,13.462 86.822,13.588 87.688,13.588 89.2,15.1 v1(92.2,15.1)
M1_IDC_Link: R16.2 R119.2 U1.56 X17.13 | length 44.9
  Top Layer w0.15: U1.56@95.225,46.275 96.775,46.275 v1(96.8,46.3) ; R16.2@107.57,49.8 R119.2@107.57,48.2 107.57,48.18 109.025,46.725 v1(109.025,46)
  Int2 (Sign) w0.15: X17.13@94.316,71.882 95.5,70.698 95.5,59.5 96,59 96,47.1 v1(96.8,46.3)
  Bottom Layer w0.15: v1(96.8,46.3) 99.1,46.3 99.3,46.1 104.528,46.1 104.628,46 v1(109.025,46)
M1_Ph_Cur_U/BEMF_U: R41.2 R118.2 U1.53 X17.16 | length 55.1
  Top Layer w0.15: U1.53@95.05,44.75 95.063,44.737 95.937,44.737 97.44,46.24 98.517,46.24 98.957,45.8 100.7,45.8 101.2,45.3 106.981,45.3 108.2,46.519 v1(108.2,46.6) ; R118.2@107.47,56.2 R41.2@107.47,55 107.554,54.916 v1(108.116,54.916)
  Int2 (Sign) w0.15: X17.16@96.856,74.422 98.271,73.007 98.271,64.843 100.4,62.714 v1(100.4,54.5)
  Int3 (Sign) w0.15: v1(108.116,54.916) 107.65,54.45 107.65,52.508 108.6,51.558 108.6,50.3 108.018,49.718 108.018,47.959 108.2,47.777 v1(108.2,46.6)
  Bottom Layer w0.15: v1(100.4,54.5) 100.425,54.525 107.725,54.525 v1(108.116,54.916)
M1_Ph_Cur_V/BEMF_V: R43.2 R117.2 U1.54 X17.18 | length 34.2
  Top Layer w0.15: U1.54@95.05,45.25 95.125,45.325 95.843,45.325 96.133,45.615 96.133,45.733 v1(96.2,45.8) ; R43.2@95.66,53.7 95.66,52.65 96.41,51.9 v1(96.5,51.9)
  Int3 (Sign) w0.15: v1(96.2,45.8) 95.862,46.138 95.862,47.762 96.1,48 96.1,51.5 v1(96.5,51.9) 96.1,52.3 96.1,64.3 98.1,66.3 98.1,72.9 99.396,74.196 X17.18@99.396,74.422
M1_Ph_Cur_W/BEMF_W: R45.2 R105.2 U1.55 X17.20 | length 40.7
  Top Layer w0.15: v1(93.7,45.8) 93.725,45.775 95.075,45.775 U1.55@95.1,45.8 ; v1(94.2,50.7) 94.7,50.2 R45.2@95.63,50.2 R105.2@95.63,51.2
  Int2 (Sign) w0.15: v1(93.7,45.8) 94.2,46.3 v1(94.2,50.7) ; v1(99.9,67.1) 100.725,67.925 100.725,73.211 X17.20@101.936,74.422
  Int3 (Sign) w0.15: v1(94.2,50.7) 94.7,51.2 94.7,60.6 94.9,60.8 94.9,67.1 v1(94.3,67.7)
  Bottom Layer w0.15: v1(94.3,67.7) 99.3,67.7 v1(99.9,67.1)
M1_VDC_Link: R148.2 R149.2 U1.57 | length 18.9
  Top Layer w0.15: v1(93.7,46.7) 93.725,46.725 95.075,46.725 U1.57@95.1,46.7 ; v1(96.5,37) 97.836,37 98.536,37.7 99.2,37.7 99.6,37.3 100.93,37.3 R148.2@101.03,37.2 R149.2@101.03,38.4
  Int2 (Sign) w0.15: v1(93.7,46.7) 93.225,46.225 93.225,44.847 94.175,43.897 94.175,41.625 96.5,39.3 v1(96.5,37)
M2_ENENC_M: JP1.2 Q9.1 Q10.1 R91.1 R93.2 U6.4 | length 60.7
  Top Layer w0.15: U6.4@68.95,15.125 71.025,15.125 73.075,17.175 73.075,17.905 R93.2@73.2,18.03 R91.1@74.2,18.03 74.23,18 74.7,18 75,18.3 75,19.9 75.5,20.4 76.7,20.4 77.2,19.9 77.2,16.7 77,16.5 v1(77,8.2) 77.55,7.65 91.95,7.65 ; Q10.1@94.05,3.75 94,3.8 93.1,3.8 92.3,4.6 92.3,7.3 91.95,7.65 ; Q9.1@94.05,8.25 92.55,8.25 91.95,7.65
  Int3 (Sign) w0.15: JP1.2@65,3.3 72.1,3.3 v1(77,8.2)
M2_HALL1/Encoder_A: R94.1 R157.1 U1.23 U6.3 X16.3 | length 69.8
  Top Layer w0.15: U6.3@68.95,15.775 70.875,15.775 v1(72.1,17) ; R94.1@72.2,18.95 v1(72.2,19.8) ; v1(83.5,35.2) 84.5,35.2 84.6,35.3 U1.23@84.6,36.8 ; v1(99.6,7.1) R157.1@100.53,7.1
  Int2 (Sign) w0.15: v1(72.2,19.8) 72.15,19.75 72.15,17.05 v1(72.1,17) 72.1,15.7 78.3,9.5 80.194,9.5 X16.3@81.616,10.922 82.9,12.206 82.9,28.63 82.6,28.93 82.6,34.3 v1(83.5,35.2)
  Int3 (Sign) w0.15: X16.3@81.616,10.922 85.438,7.1 v1(99.6,7.1)
M2_HALL2/Encoder_B: R95.1 R159.1 U1.24 U6.5 X16.5 | length 75.5
  Top Layer w0.15: U6.5@68.95,14.475 68.975,14.5 v1(72.1,14.5) ; v1(72.1,8.8) 72.1,9.95 R95.1@72.2,10.05 ; U1.24@85.1,36.8 v1(85.1,38.1) ; v1(102.75,7.1) R159.1@103.43,7.1
  Int2 (Sign) w0.15: v1(72.1,14.5) v1(72.1,8.8) 73.6,7.3 80.534,7.3 X16.5@84.156,10.922 ; v1(85.1,38.1) 85.1,38.005 84.3,37.205 84.3,34.6 83.6,33.9 83.6,29.7 85.3,28 85.3,12.066 X16.5@84.156,10.922 ; v1(102.75,7.1) 101.75,8.1 86.978,8.1 X16.5@84.156,10.922
M2_HALL3/Encoder_Z/Index: R96.1 R160.1 U1.25 U6.11 X16.7 | length 69.6
  Top Layer w0.15: v1(73.2,9.3) R96.1@73.2,10.05 ; v1(73.2,13.9) 74.675,13.9 U6.11@74.75,13.825 ; v1(85.6,35.5) U1.25@85.6,36.8 ; v1(105.5,7.1) R160.1@106.33,7.1 R160.1@106.3,7.13
  Int2 (Sign) w0.15: v1(73.2,9.3) v1(73.2,13.9) ; X16.7@86.696,10.922 88.618,9 103.6,9 v1(105.5,7.1)
  Int3 (Sign) w0.15: v1(85.6,35.5) 85.6,29.6 85.1,29.1 85.1,14.6 85.4,14.3 85.4,12.218 X16.7@86.696,10.922
  Bottom Layer w0.15: v1(73.2,9.3) 73.75,8.75 84.524,8.75 X16.7@86.696,10.922
M2_IDC_Link: R55.2 R136.2 U1.64 X17.15 | length 39.2
  Top Layer w0.15: v1(91.6,48.9) U1.64@91.6,50.2 ; v1(101.4,58.7) 102.2,59.5 R136.2@104.03,59.5 R55.2@104.03,60.5
  Int2 (Sign) w0.15: v1(91.5,57.1) 91.55,57.05 91.55,48.95 v1(91.6,48.9) ; v1(99,69.8) 99,64.6 101.4,62.2 v1(101.4,58.7)
  Bottom Layer w0.15: v1(91.5,57.1) 91.548,57.052 94.924,57.052 95.947,58.075 98.753,58.075 99.378,58.7 v1(101.4,58.7) ; X17.15@96.856,71.882 96.887,71.882 98.969,69.8 v1(99,69.8)
M2_Ph_Cur_U/BEMF_U: R57.2 R125.2 U1.61 X17.22 | length 40.2
  Top Layer w0.15: U1.61@93.1,50.2 v1(93.1,51.3) ; X17.22@104.476,74.422 103.2,73.146 103.2,71.3 104.083,70.417 105.042,70.417 106.44,69.02 R125.2@106.44,69 106.47,68.97 R57.2@106.47,68 106.47,67.47 v1(106.2,67.2)
  Int2 (Sign) w0.15: v1(93.1,51.3) v1(93.1,59.2)
  Int3 (Sign) w0.15: v1(105.6,58.9) 105.6,58.972 105.3,59.272 105.3,66.3 v1(106.2,67.2)
  Bottom Layer w0.15: v1(93.1,59.2) 105.228,59.2 105.528,58.9 v1(105.6,58.9)
M2_Ph_Cur_V/BEMF_V: R59.2 R124.2 U1.62 X17.24 | length 45.1
  Top Layer w0.15: v1(92.2,69.5) 94.33,69.5 94.795,69.035 94.815,69.035 95.03,68.82 R124.2@95.03,68.8 R59.2@95.03,67.7 ; v1(92.6,48.9) U1.62@92.6,50.2
  Int2 (Sign) w0.15: v1(92.6,48.9) 92.6,48.963 92.4,49.163 92.4,51.128 92.625,51.353 92.625,59.397 92.8,59.572 92.8,68.8 92.2,69.4 v1(92.2,69.5) 92.901,70.201 v1(92.9,73) v1(92.9,73)
  Bottom Layer w0.15: v1(92.9,73) 92.907,73.007 105.493,73.007 106.908,74.422 X17.24@107.016,74.422
M2_Ph_Cur_W/BEMF_W: R61.2 R123.2 U1.63 X17.26 | length 49.4
  Top Layer w0.15: U1.63@92.1,50.2 v1(92.1,51.5) ; v1(92.127,57.527) 95.399,57.527 95.997,58.125 98.197,58.125 98.953,58.881 98.953,59.483 R123.2@98.97,59.5 R61.2@98.97,60.4 ; v1(108.2,68.3) 108.2,73.066 X17.26@109.556,74.422
  Int2 (Sign) w0.15: v1(92.1,51.5) 92.15,51.55 92.15,67.75 v1(92.2,67.8)
  Bottom Layer w0.15: v1(92.2,67.8) 93.6,67.8 94,68.2 107.937,68.2 107.97,68.233 108.133,68.233 v1(108.2,68.3)
NetC12_1: C12.1 U2.4 | length 9.6
  Top Layer w0.3: C12.1@36.165,71.44 C12.1@36.431,71.706 ; C12.1@36.331,71.706 C12.1@36.406,71.706 ; C12.1@36.34,71.6 38.5,71.6 ; C12.1@36.406,71.6 38.4,71.6 39.1,72.3 39.1,74.03 38.005,75.125 37.905,75.225 U2.4@37.905,75.375 ; U2.4@37.905,75.555 U2.4@37.905,75.375 ; U2.4@38.08,75.2 37.98,75.3 U2.4@37.905,75.375
NetC18_2: C18.2 U1.10 | length 4.5
  Top Layer w0.2: C18.2@78.4,46 78.875,45.525 78.875,45.025 80.15,43.75 U1.10@81.65,43.75
NetC28_2: C28.2 R5.1 R126.1 SW1.3 SW1.4 | length 21.6
  Top Layer w0.15: R5.1@44.69,6.8 44.69,6.665 45.455,5.9 46.6,5.9 46.8,6.1 46.8,6.74 C28.2@46.86,6.8 R126.1@48.04,6.8 48.04,14.71 48,14.75
  Top Layer w0.3: SW1.4@41.65,14.75 48,14.75 SW1.3@50.75,14.75
NetC41_1: C41.1 U8.4 | length 1.6
  Top Layer w0.3: C41.1@22.7,29.14 22.703,29.143 U8.4@22.703,30.752 ; U8.4@22.7,30.75 U8.4@22.703,30.752 ; U8.4@22.705,30.755 U8.4@22.703,30.752
NetC62_2: C62.2 L5.2 L6.2 U20.2 | length 12.7
  Top Layer w1: C62.2@24.9,24.8 24.908,24.807 30.492,24.807 L6.2@30.5,24.815 31.71,24.815 33.43,26.535 U20.2@33.43,29.845 ; L5.2@27,24.7 L5.2@27.15,24.7
NetC74_1: C74.1 R84.1 | length 8.7
  Top Layer w0.2: v1(72.1,68.9) 72.1,69.66 C74.1@72.14,69.7 ; v1(72.1,73.5) 72.148,73.452 72.548,73.452 72.8,73.2 72.8,71.417 72.683,71.3 R84.1@72.17,71.3
  Int2 (Sign) w0.2: v1(72.1,68.9) v1(72.1,73.5)
NetC85_2: C85.2 R8.2 Y1.1 | length 2.6
  Top Layer w0.2: Y1.1@76.65,39.125 77.67,39.125 78.045,39.5 C85.2@78.06,39.5 78.05,39.49 R8.2@78.05,38.5
NetC87_2: C87.2 R23.1 Y2.1 | length 2.5
  Top Layer w0.15: R23.1@25.1,17.53 25.13,17.56 C87.2@26.1,17.56 Y2.1@26.1,16.175 ; Y2.1@26.05,15.725 Y2.1@26.1,15.775
NetC88_2: C88.2 U7.30 Y2.3 | length 11.3
  Top Layer w0.15: U7.30@22,19.75 22.025,19.725 22.975,19.725 v1(23,19.7) ; v1(22.4,13.8) Y2.3@23.675,13.8 ; Y2.3@23.75,13.875 Y2.3@23.675,13.8 ; C88.2@24.398,12.002 24.398,12.21 24.21,12.398 24.002,12.398 23.747,12.653 23.747,13.728 Y2.3@23.675,13.8
  Bottom Layer w0.15: v1(22.4,13.8) 22.998,13.8 23.175,13.977 23.175,18.127 23,18.302 v1(23,19.7)
NetC89_1: C89.1 R85.1 | length 4.5
  Top Layer w0.2: C89.1@68.14,72.6 v1(68.9,72.6) ; R85.1@68.17,69.7 68.27,69.8 v1(68.8,69.8)
  Bottom Layer w0.2: v1(68.8,69.8) 68.8,70.493 68.5,70.793 68.5,72.2 v1(68.9,72.6)
NetC90_1: C90.1 R86.1 | length 3.3
  Top Layer w0.15: C90.1@68.14,57.7 v1(69,57.7) ; R86.1@68.17,59.3 v1(69,59.3)
  Int2 (Sign) w0.15: v1(69,57.7) v1(69,59.3)
NetC94_1: C94.1 R100.1 | length 4.6
  Top Layer w0.15: R100.1@71.2,18.97 v1(71.2,19.8)
  Top Layer w0.2: v1(68.7,18.9) C94.1@69.6,18.9
  Bottom Layer w0.15: v1(68.7,18.9) 70.3,18.9 v1(71.2,19.8)
NetC95_1: C95.1 R101.1 | length 3.3
  Top Layer w0.15: v1(69.6,9.2) C95.1@69.6,10.06 ; v1(71.2,9.2) R101.1@71.2,10.03
  Int3 (Sign) w0.15: v1(69.6,9.2) v1(71.2,9.2)
NetC96_1: C96.1 R102.1 | length 3.2
  Top Layer w0.15: v1(74.2,9.3) R102.1@74.2,10.03 ; v1(75.8,9.3) 75.8,9.928 C96.1@75.886,10.014
  Top Layer w0.2: C96.1@75.82,10.08 C96.1@75.886,10.014
  Top Layer w0.3: C96.1@75.8,10.06 C96.1@75.82,10.08
  Int3 (Sign) w0.15: v1(74.2,9.3) v1(75.8,9.3)
NetC126_1: C126.1 U14.4 | length 2.4
  Top Layer w0.5: U14.4@36.795,54.045 36.795,54.375 38.16,55.74 38.2,55.74 C126.1@38.26,55.8
NetC137_1: C137.1 R50.2 R51.1 SW2.3 SW2.4 | length 21.9
  Top Layer w0.15: R50.2@54.67,6.8 54.67,6.23 55.1,5.8 56.4,5.8 56.74,6.14 C137.1@56.74,6.8 R51.1@57.93,6.8 57.93,14.72 57.9,14.75
  Top Layer w0.3: SW2.4@54.45,14.75 57.9,14.75 SW2.3@63.55,14.75
NetD1_1: D1.1 R109.1 | length 1.5
  Top Layer w0.15: D1.1@50.55,2.5 50.55,3.95 R109.1@50.6,4
NetD2_1: D2.1 R110.1 | length 1.5
  Top Layer w0.15: R110.1@58.8,4 58.85,3.95 D2.1@58.85,2.5
NetD3_1: D3.1 R111.1 | length 1.6
  Top Layer w0.15: R111.1@26.6,81.6 26.65,81.65 D3.1@26.65,83.2
NetD4_2: D4.2 R112.2 | length 1.5
  Top Layer w0.15: R112.2@12.3,27 12.35,26.95 D4.2@12.35,25.5
NetD5_2: D5.2 R113.1 | length 2.2
  Top Layer w0.15: D5.2@14.75,25.5 15.075,25.825 15.125,25.825 15.9,26.6 15.975,26.6 16.3,26.925 R113.1@16.3,27
NetL3_1: L3.1 U16.10 U16.11 | length 5.9
  Top Layer w0.3: L3.1@58.45,73.335 L3.1@58.5,73.285 58.76,73.285 59.1,73.625 U16.11@59.1,75.7 U16.10@58.45,75.7 L3.1@58.45,73.335
NetQ1_3: Q1.3 R114.2 R115.2 R116.2 | length 15.8
  Top Layer w0.3: Q1.3@95.95,82.2 95.95,81.65 v1(96.3,81.3) ; R116.2@100.97,78.8 102.3,78.8 ; v1(102.3,81.3) 102.3,78.8 ; R114.2@105.83,78.8 105.8,78.77 105.8,78.2 105.6,78 103.406,78 103.23,78.176 R115.2@103.23,78.8 102.3,78.8
  Int2 (Sign) w0.3: v1(96.3,81.3) v1(102.3,81.3)
NetQ2_2: Q2.2 Q2.5 R64.1 | length 3.8
  Top Layer w0.2: R64.1@46.17,75.8 Q2.5@49.95,75.8
NetQ2_3: Q2.3 Q3.1 R65.2 | length 15.7
  Top Layer w0.2: R65.2@46.17,74.82 R65.2@46.17,74.8 ; Q2.3@48.05,75.15 47.725,75.15 47.375,74.8 R65.2@46.17,74.8 ; Q3.1@51.615,76.95 51.565,77 50.6,77 50,77.6 44.9,77.6 43.7,76.4 43.7,74.8 44.4,74.1 46,74.1 46.17,74.27 R65.2@46.17,74.8
NetQ2_6: Q2.6 R63.2 | length 4.3
  Top Layer w0.2: R63.2@46.17,76.8 46.17,76.82 46.36,77.01 46.38,77.01 46.57,77.2 48.875,77.2 49.625,76.45 Q2.6@49.95,76.45
NetQ4_1: Q4.1 Q5.3 R66.2 | length 15.7
  Top Layer w0.2: R66.2@46.17,70.52 R66.2@46.17,70.5 ; Q5.3@48.05,70.85 47.725,70.85 47.375,70.5 R66.2@46.17,70.5 ; Q4.1@51.615,72.65 51.565,72.7 50.6,72.7 50,73.3 44.9,73.3 43.7,72.1 43.7,70.5 44.4,69.8 46,69.8 46.17,69.97 R66.2@46.17,70.5
NetQ5_2: Q5.2 Q5.5 R54.1 | length 3.8
  Top Layer w0.2: R54.1@46.17,71.5 Q5.5@49.95,71.5
NetQ5_6: Q5.6 R52.2 | length 4.3
  Top Layer w0.2: R52.2@46.17,72.5 46.17,72.52 46.36,72.71 46.38,72.71 46.57,72.9 48.875,72.9 49.625,72.15 Q5.6@49.95,72.15
NetQ6_1: Q6.1 Q7.3 R67.2 | length 15.7
  Top Layer w0.2: R67.2@46.17,66.22 R67.2@46.17,66.2 ; Q7.3@48.05,66.55 47.725,66.55 47.375,66.2 R67.2@46.17,66.2 ; Q6.1@51.615,68.35 51.565,68.4 50.6,68.4 50,69 44.9,69 43.7,67.8 43.7,66.2 44.4,65.5 46,65.5 46.17,65.67 R67.2@46.17,66.2
NetQ7_2: Q7.2 Q7.5 R68.1 | length 3.8
  Top Layer w0.2: R68.1@46.17,67.2 Q7.5@49.95,67.2
NetQ7_6: Q7.6 R69.2 | length 4.3
  Top Layer w0.2: R69.2@46.17,68.2 46.17,68.22 46.36,68.41 46.38,68.41 46.57,68.6 48.875,68.6 49.625,67.85 Q7.6@49.95,67.85
NetQ8_3: Q8.3 X3.1 | length 15.9
  Top Layer w0.5: Q8.3@95.95,79.1 96.3,79.1 99.1,81.9 v1(99.1,82.4)
  Int2 (Sign) w0.5: v1(99.1,82.4) 108.08,82.4 X3.1@109.58,83.9
NetQ9_3: Q9.3 R120.2 R121.2 R122.2 | length 12.7
  Top Layer w0.3: Q9.3@95.95,7.6 97,7.6 97.6,8.2 R120.2@100.53,8.2 100.6,8.27 100.6,8.8 100.8,9 103.4,9 ; R121.2@103.43,8.2 103.43,8.97 103.4,9 ; R122.2@106.33,8.2 106.3,8.23 106.3,8.7 106,9 103.4,9
NetQ10_3: Q10.3 X7.1 | length 3.5
  Top Layer w0.5: Q10.3@95.95,3.1 97.56,3.1 ; 97.56,3.1 X7.1@99.42,3.1
NetR3_1: R3.1 X11.5 | length 2.5
  Top Layer w0.15: X11.5@63.365,35.965 63.55,35.78 R3.1@63.55,33.5
NetR6_2: R6.2 R9.1 | length 17.5
  Top Layer w0.15: R9.1@44.6,31.94 46.36,31.94 50.5,27.8 R6.2@50.5,17.9
NetR7_2: R7.2 R10.1 | length 16.2
  Top Layer w0.15: R7.2@62.9,17.9 62.9,25.5 66.4,29 R10.1@70.04,29
NetR11_2: R11.2 X1.10 X12.10 | length 53.8
  Top Layer w0.15: X12.10@66.6,51.4 v1(66.6,53.54) ; R11.2@86.45,30.5 86.45,30.05 87.1,29.4 v1(87.6,29.4) 87.6,27.6 X1.10@87.665,27.535
  Int2 (Sign) w0.15: v1(66.6,53.54) 69.1,51.04 69.1,49.1 68.6,48.6 68.6,29.7 v1(67.2,28.3)
  Bottom Layer w0.15: v1(67.2,28.3) 86.5,28.3 v1(87.6,29.4)
NetR18_2: R18.2 X10.A5 | length 2.3
  Top Layer w0.2: X10.A5@11.63,36.25 11.68,36.3 12.4,36.3 13.067,36.967 13.577,36.967 R18.2@13.61,37
NetR21_1: R21.1 X10.B5 | length 6.3
  Top Layer w0.2: X10.B5@9.634,34.654 X10.B5@9.68,34.7 9.596,34.7 9.055,34.159 9.055,32.836 10.81,31.081 R21.1@10.81,29.5
NetR22_1: R22.1 R24.2 U7.7 | length 10.4
  Top Layer w0.15: R22.1@7.802,20.262 7.812,20.272 R24.2@8.922,20.272 ; R24.2@8.902,20.272 9.53,20.272 9.7,20.102 9.7,18.502 10.237,17.965 12.763,17.965 12.765,17.967 13.163,17.967 13.165,17.965 13.558,17.965 13.8,18.207 13.8,18.23 13.9,18.33 13.9,19.2 14.463,19.763 14.987,19.763 U7.7@15,19.75
NetR23_2: R23.2 U7.29 | length 3.6
  Top Layer w0.15: U7.29@22,19.25 22.65,19.25 22.81,19.09 24.812,19.09 25.005,18.897 25.005,18.565 R23.2@25.1,18.47
NetR28_2: R28.2 X19.5 | length 2.7
  Top Layer w0.15: X19.5@114.636,56.642 115.794,57.8 R28.2@116.83,57.8
NetR29_1: R29.1 X19.6 | length 2.2
  Top Layer w0.15: R29.1@109.87,56.6 109.912,56.642 X19.6@112.07,56.642
NetR30_2: R30.2 X19.15 | length 2.2
  Top Layer w0.15: X19.15@114.636,43.942 116.772,43.942 R30.2@116.83,44
NetR31_1: R31.1 X19.16 | length 4
  Top Layer w0.15: R31.1@108.53,44.1 108.53,44.08 109.045,43.565 110.265,43.565 110.7,44 112.012,44 X19.16@112.07,43.942
NetR32_2: R32.2 X19.29 | length 2.2
  Top Layer w0.15: X19.29@114.61,26.162 116.792,26.162 R32.2@116.83,26.2
NetR33_1: R33.1 X19.30 | length 7.2
  Top Layer w0.15: X19.30@112.07,26.162 113.308,27.4 115.5,27.4 116.1,28 116.1,29.35 116.83,30.08 R33.1@116.83,30.1
NetR48_1: R48.1 R103.2 X18.12 | length 17.7
  Top Layer w0.15: R48.1@17.63,77.1 17.7,77.03 X18.12@17.7,74.5 17.7,72.2 18.05,71.85 R103.2@18.05,59.6
NetR49_1: R49.1 R104.2 X18.11 | length 17.7
  Top Layer w0.15: R49.1@20.33,77.1 20.24,77.01 X18.11@20.24,74.5 20.24,72.16 20.55,71.85 R104.2@20.55,59.6
NetR73_1: R73.1 X28.2 | length 3.1
  Top Layer w0.2: R73.1@19.97,5.97 20.23,5.71 X28.2@20.23,3
NetR106_1: R106.1 U16.12 | length 4.9
  Top Layer w0.15: v1(59.7,74.5) 59.7,75.65 U16.12@59.75,75.7 ; v1(62,73.6) R106.1@63.03,73.6
  Int2 (Sign) w0.15: v1(59.7,74.5) 60.6,73.6 v1(62,73.6)
NetR107_1: R107.1 U16.5 | length 2
  Top Layer w0.2: U16.5@58.45,81.1 58.51,81.16 58.51,83.04 R107.1@58.57,83.1
NetR108_2: R108.2 U16.13 | length 4
  Top Layer w0.15: v1(60.4,74.5) U16.13@60.4,75.7 ; v1(62,74.4) 62.95,74.4 R108.2@63.05,74.5
  Int2 (Sign) w0.15: v1(60.4,74.5) 60.425,74.525 61.117,74.525 61.242,74.4 v1(62,74.4)
NetR114_1: R114.1 R151.2 X3.2 | length 5
  Top Layer w0.15: R114.1@106.77,78.8 R151.2@106.77,80 ; R151.2@106.77,80.2 106.77,82.47 107.04,82.74 X3.2@107.04,83.9
NetR115_1: R115.1 R153.2 X3.3 | length 6
  Top Layer w0.15: R115.1@104.17,78.8 104.17,78.82 103.445,79.545 103.445,79.785 R153.2@103.23,80 103.23,80.83 104.5,82.1 X3.3@104.5,83.9
NetR116_1: R116.1 R155.2 X3.4 | length 5.6
  Top Layer w0.15: R116.1@100.03,79.1 100.03,80.1 100.03,81.97 X3.4@101.96,83.9
NetR120_1: R120.1 R157.2 X7.2 | length 5.3
  Top Layer w0.2: R120.1@101.47,8.2 R157.2@101.47,7.1 101.47,5.63 101.96,5.14 X7.2@101.96,3.1
NetR121_1: R121.1 R159.2 X7.3 | length 5.2
  Top Layer w0.2: R121.1@104.37,8.2 R159.2@104.37,7.1 104.435,7.035 104.435,3.165 X7.3@104.5,3.1
NetR122_1: R122.1 R160.2 X7.4 | length 5.2
  Top Layer w0.2: X7.4@107.04,3.1 107.04,5.54 107.3,5.8 107.3,7.07 R160.2@107.27,7.1 R122.1@107.27,8.2
NetR128_2: R128.2 SW3.1 U17.1 U17.5 | length 25.6
  Top Layer w0.15: v1(53.9,56.2) U17.1@55,56.2 56.15,56.2 56.43,55.92 R128.2@56.43,55.9 ; v1(53.9,58.2) U17.5@54.896,58.2 ; v1(55.2,39.7) 57.06,39.7 SW3.1@57.1,39.66
  Bottom Layer w0.15: v1(53.9,58.2) v1(53.9,56.2) 53.9,52.4 52.7,51.2 52.7,50.7 54.6,48.8 54.6,41.3 55.2,40.7 v1(55.2,39.7)
NetR129_2: R129.2 SW3.2 U18.1 U18.5 | length 18.4
  Top Layer w0.15: v1(53.2,53) U18.5@55,53 R129.2@56.43,53 ; v1(53.4,50.9) 53.425,50.925 53.875,50.925 53.95,51 U18.1@55,51 ; v1(55.2,42.2) SW3.2@57.1,42.2
  Int2 (Sign) w0.15: v1(53.2,53) 53.2,51.195 53.4,50.995 v1(53.4,50.9)
  Bottom Layer w0.15: v1(53.4,50.9) 53.4,50.805 53.536,50.669 53.536,50.664 55.2,49 v1(55.2,42.2)
NetR130_2: R130.2 SW3.3 U19.1 U19.5 | length 24.3
  Top Layer w0.15: U19.1@54.896,61.5 U19.1@55,61.5 56.33,61.5 R130.2@56.43,61.6 ; U19.5@55,63.5 56.2,63.5 56.575,63.125 56.575,61.745 R130.2@56.43,61.6 ; SW3.3@57.16,44.8 v1(58.8,44.8) ; v1(57.4,60.2) 56.447,61.153 56.447,61.583 R130.2@56.43,61.6
  Bottom Layer w0.15: v1(57.4,60.2) 57.4,46.2 v1(58.8,44.8)
NetR131_1: R131.1 R132.2 U14.2 | length 4.4
  Top Layer w0.2: U14.2@39.335,54.045 39.335,53.715 40.08,52.97 R132.2@42,52.97 R131.1@42,54.03
NetR133_1: R133.1 R134.2 U2.2 | length 3.7
  Top Layer w0.3: U2.2@35.365,75.885 U2.2@35.365,75.555 35.365,75.225 36.23,74.36 36.23,73.84 R133.1@36.37,73.7 R134.2@37.43,73.7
